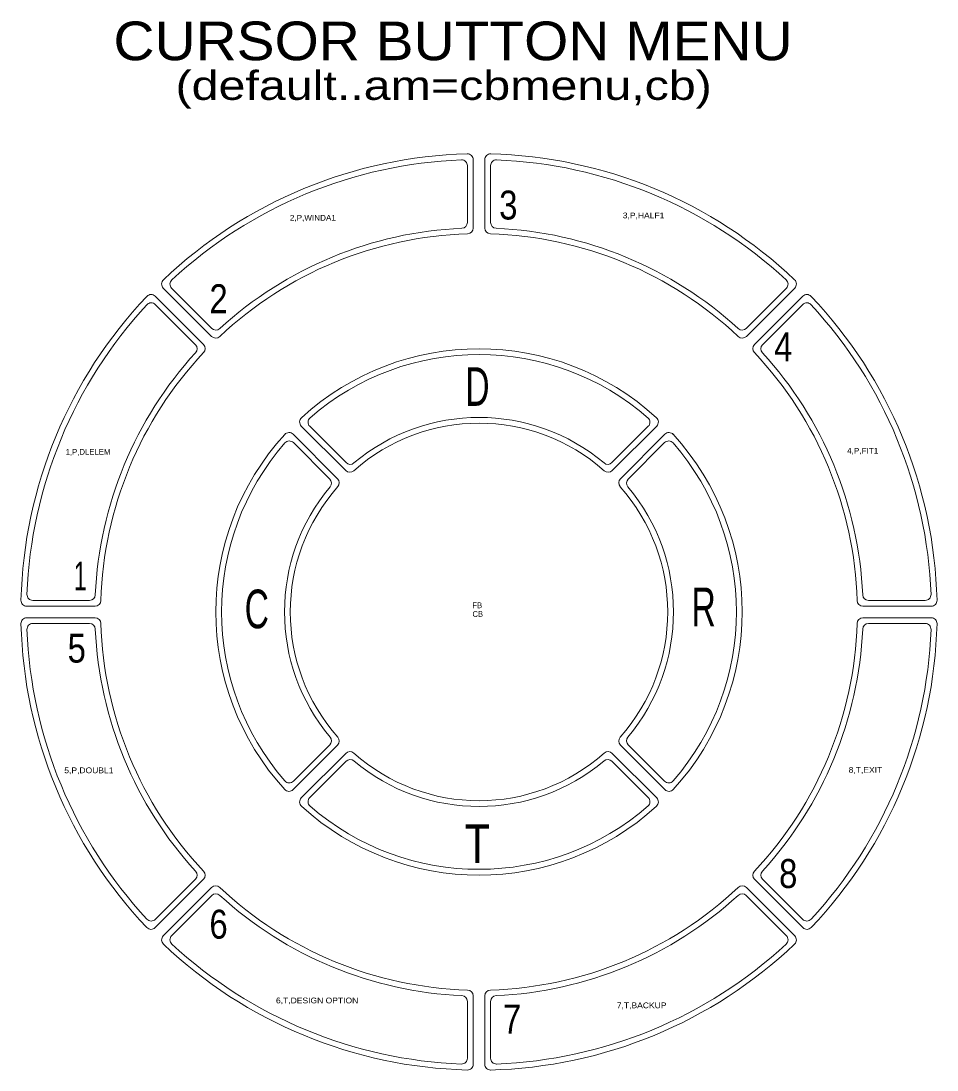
# Model space of a CAD drawing. Extents: x -1.2 to 59.9, y -11 to 7.1.
# Drawn here: x 44.08 to 59.91, y -11.04 to 7.09 of the extents above; entities that cross this region are included whole.
import ezdxf

# ---------------------------------------------------------------- set-up
doc = ezdxf.new("R2010")
doc.units = 0
doc.header["$LTSCALE"] = 0.2
for name, color, linetype, lineweight in [('1', 7, 'Continuous', 13), ('10', 7, 'Continuous', 13), ('4', 7, 'Continuous', 13)]:
    doc.layers.add(name, color=color, linetype=linetype, lineweight=lineweight)
doc.layers.add('63', color=7, linetype='Continuous')

msp = doc.modelspace()

# ---------------------------------------------------------------- linework, layer by layer
at = {"layer": '1'}
for p, q in [((51.7948, 4.5906), (51.7948, 3.609)), ((51.8948, 4.6939), (51.8948, 3.5127)), ((52.0948, 3.5127), (52.0948, 4.6939)), ((52.1948, 3.609), (52.1948, 4.5906)), ((47.3748, 1.6405), (46.5396, 2.4757)), ((47.3775, 1.7794), (46.6834, 2.4735)), ((57.3064, 2.4734), (56.6123, 1.7793)), ((57.4501, 2.4757), (56.6148, 1.6404)), ((47.2333, 1.499), (46.3981, 2.3342)), ((47.0945, 1.4964), (46.4004, 2.1905)), ((57.5916, 2.3342), (56.7563, 1.4989)), ((57.5893, 2.1905), (56.8952, 1.4964)), ((48.9241, 0.0912), (49.6931, -0.6778)), ((49.0697, 0.087), (49.6981, -0.5414)), ((54.92, 0.087), (54.2916, -0.5414)), ((55.0655, 0.0911), (54.2966, -0.6778)), ((49.5516, -0.8193), (48.7826, -0.0503)), ((54.4381, -0.8193), (55.207, -0.0504)), ((49.4152, -0.8243), (48.7868, -0.1959)), ((54.5745, -0.8243), (55.2029, -0.1959)), ((45.361, -3.0211), (44.1798, -3.0211)), ((45.2647, -2.9211), (44.2831, -2.9211)), ((58.6286, -3.0211), (59.8098, -3.0211)), ((58.7249, -2.9211), (59.7065, -2.9211)), ((45.361, -3.2211), (44.1798, -3.2211)), ((58.6286, -3.2211), (59.8098, -3.2211)), ((45.2647, -3.3211), (44.2831, -3.3211)), ((58.7249, -3.3211), (59.7065, -3.3211)), ((49.5515, -5.4229), (48.7826, -6.1918)), ((49.4151, -5.4179), (48.7867, -6.0463)), ((55.2071, -6.1918), (54.4381, -5.4228)), ((55.2029, -6.0462), (54.5745, -5.4178)), ((48.9241, -6.3334), (49.6931, -5.5644)), ((55.0655, -6.3333), (54.2966, -5.5644)), ((49.0697, -6.3292), (49.6981, -5.7008)), ((54.92, -6.3292), (54.2916, -5.7008)), ((47.2333, -7.7411), (46.398, -8.5764)), ((47.0944, -7.7386), (46.4003, -8.4327)), ((56.7564, -7.7411), (57.5916, -8.5763)), ((56.8952, -7.7385), (57.5893, -8.4326)), ((47.3748, -7.8827), (46.5396, -8.7179)), ((57.4501, -8.7179), (56.6148, -7.8826)), ((47.3775, -8.0216), (46.6834, -8.7157)), ((57.3064, -8.7156), (56.6123, -8.0215)), ((51.8948, -10.9361), (51.8948, -9.7549)), ((52.0948, -9.7549), (52.0948, -10.9361)), ((51.7948, -10.8328), (51.7948, -9.8512)), ((52.1948, -9.8512), (52.1948, -10.8328))]:
    msp.add_line(p, q, dxfattribs=at)
for centre, radius, start, end in [((51.9948, -3.1211), 7.9175, 91.46599, 133.53309), ((51.7948, 4.6939), 0.1, 0, 91.46599), ((52.1948, 4.6939), 0.1, 88.53401, 180), ((51.9948, -3.1211), 7.9175, 46.46106, 88.59887), ((51.9948, -3.1211), 7.8175, 92.22779, 132.77033), ((51.6948, 4.5906), 0.1, 0, 92.22779), ((52.2948, 4.5906), 0.1, 87.77221, 180), ((51.9948, -3.1211), 7.8175, 47.22851, 87.82053), ((51.9948, -3.1211), 6.6368, 92.55191, 132.44564), ((51.6948, 3.609), 0.1, 272.55231, 0), ((51.7948, 3.5127), 0.1, 271.72687, 0), ((52.1948, 3.5127), 0.1, 180, 268.27313), ((52.2948, 3.609), 0.1, 180, 267.44769), ((51.9948, -3.1211), 6.6368, 47.55266, 87.44769), ((51.9948, -3.1211), 6.5368, 91.727, 133.27177), ((51.9948, -3.1211), 6.5368, 46.72735, 88.27313), ((46.6103, 2.5464), 0.1, 133.53309, 225), ((46.7541, 2.5442), 0.1, 132.77033, 225), ((57.2356, 2.5441), 0.1, 315, 47.22809), ((57.3794, 2.5464), 0.1, 315, 46.46639), ((46.3274, 2.2635), 0.1, 45, 136.46587), ((57.6623, 2.2635), 0.1, 43.53361, 135), ((46.3297, 2.1198), 0.1, 45, 137.22757), ((57.66, 2.1197), 0.1, 42.77191, 135), ((47.4455, 1.7112), 0.1, 225, 313.27204), ((47.4482, 1.8501), 0.1, 225, 312.44554), ((56.5415, 1.85), 0.1, 227.55266, 315), ((56.5441, 1.7112), 0.1, 226.72735, 315), ((47.0238, 1.4257), 0.1, 317.55206, 45), ((47.1626, 1.4283), 0.1, 316.72674, 45), ((56.8271, 1.4282), 0.1, 135, 223.27265), ((56.9659, 1.4256), 0.1, 135, 222.44734), ((48.9949, 0.1619), 0.1, 132.42079, 225), ((49.1404, 0.1577), 0.1, 131.04141, 225), ((54.8492, 0.1577), 0.1, 315, 48.95766), ((54.9948, 0.1618), 0.1, 315, 47.5783), ((48.7119, -0.121), 0.1, 45, 137.57739), ((48.7161, -0.2666), 0.1, 45, 138.95673), ((55.2736, -0.2667), 0.1, 41.04234, 135), ((55.2777, -0.1211), 0.1, 42.4217, 135), ((49.7688, -0.4707), 0.1, 225, 310.02579), ((54.2209, -0.4707), 0.1, 229.97303, 315), ((49.7638, -0.6071), 0.1, 225, 311.58658), ((54.2259, -0.6071), 0.1, 228.41221, 315), ((49.3445, -0.895), 0.1, 319.97186, 45), ((49.4809, -0.89), 0.1, 318.411, 45), ((54.5088, -0.89), 0.1, 135, 221.58779), ((54.6452, -0.895), 0.1, 135, 220.02697), ((44.2831, -2.8211), 0.1, 177.77221, 270), ((45.2647, -2.8211), 0.1, 270, 357.44769), ((58.7249, -2.8211), 0.1, 182.55231, 270), ((59.7065, -2.8211), 0.1, 270, 2.22779), ((44.1798, -2.9211), 0.1, 178.53401, 270), ((45.361, -2.9211), 0.1, 270, 358.27313), ((58.6286, -2.9211), 0.1, 181.72687, 270), ((59.8098, -2.9211), 0.1, 270, 1.46599), ((44.1798, -3.3211), 0.1, 90, 181.46599), ((45.361, -3.3211), 0.1, 1.72687, 90), ((58.6286, -3.3211), 0.1, 90, 178.27313), ((59.8098, -3.3211), 0.1, 358.53401, 90), ((44.2831, -3.4211), 0.1, 90, 182.22779), ((45.2647, -3.4211), 0.1, 2.55231, 90), ((58.7249, -3.4211), 0.1, 90, 177.44769), ((59.7065, -3.4211), 0.1, 357.77221, 90), ((49.3444, -5.3472), 0.1, 315, 40.02697), ((49.4808, -5.3522), 0.1, 315, 41.58779), ((54.5088, -5.3521), 0.1, 138.41342, 225), ((54.6452, -5.3471), 0.1, 139.97421, 225), ((49.7638, -5.6351), 0.1, 48.41342, 135), ((54.2259, -5.6351), 0.1, 45, 131.58779), ((49.7688, -5.7715), 0.1, 49.97421, 135), ((54.2209, -5.7715), 0.1, 45, 130.02697), ((48.716, -5.9755), 0.1, 221.04234, 315), ((55.2736, -5.9755), 0.1, 225, 318.95859), ((48.7119, -6.1211), 0.1, 222.4217, 315), ((48.9949, -6.4041), 0.1, 135, 227.57921), ((49.1404, -6.3999), 0.1, 135, 228.95859), ((54.8492, -6.3999), 0.1, 311.04234, 45), ((54.9948, -6.404), 0.1, 312.4217, 45), ((55.2778, -6.121), 0.1, 225, 317.57921), ((47.0237, -7.6678), 0.1, 315, 42.44734), ((47.1625, -7.6704), 0.1, 315, 43.27265), ((56.8271, -7.6704), 0.1, 136.72796, 225), ((56.9659, -7.6678), 0.1, 137.55326, 225), ((47.4455, -7.9534), 0.1, 46.72796, 135), ((51.9948, -3.1211), 6.5368, 226.72823, 268.273), ((51.9948, -3.1211), 6.5368, 271.72687, 313.27265), ((56.5441, -7.9534), 0.1, 45, 133.27265), ((47.4482, -8.0923), 0.1, 47.55446, 135), ((51.9948, -3.1211), 6.6368, 227.55436, 267.44809), ((51.9948, -3.1211), 6.6368, 272.55231, 312.44734), ((56.5415, -8.0922), 0.1, 45, 132.44734), ((46.3296, -8.3619), 0.1, 222.77191, 315), ((57.66, -8.3619), 0.1, 225, 317.22862), ((46.3273, -8.5057), 0.1, 223.53361, 315), ((57.6623, -8.5056), 0.1, 225, 316.46691), ((46.6103, -8.7886), 0.1, 135, 226.46691), ((51.9948, -3.1211), 7.9175, 226.46691, 268.53401), ((46.7541, -8.7864), 0.1, 135, 227.22967), ((51.9948, -3.1211), 7.8175, 227.22967, 267.77221), ((51.9948, -3.1211), 7.9175, 271.40113, 313.53894), ((51.9948, -3.1211), 7.8175, 272.17947, 312.77149), ((57.2356, -8.7863), 0.1, 312.77191, 45), ((57.3794, -8.7886), 0.1, 313.53361, 45), ((51.6948, -9.8512), 0.1, 0, 87.44769), ((51.7948, -9.7549), 0.1, 0, 88.27313), ((52.1948, -9.7549), 0.1, 91.72687, 180), ((52.2948, -9.8512), 0.1, 92.55231, 180), ((51.6948, -10.8328), 0.1, 267.77221, 0), ((52.2948, -10.8328), 0.1, 180, 272.22779), ((51.7948, -10.9361), 0.1, 268.53401, 0), ((52.1948, -10.9361), 0.1, 180, 271.46599)]:
    msp.add_arc(centre, radius, start, end, dxfattribs=at)
at = {"layer": '10'}
for radius, start, end in [(7.9175, 136.46588, 178.53401), (7.8175, 137.22757, 177.77221), (7.8175, 2.19928, 42.80053), (7.9175, 1.46599, 43.5333), (6.6368, 137.55192, 177.44809), (6.5368, 136.72699, 178.273), (4.5472, 47.57756, 132.42066), (4.4472, 48.86849, 131.04218), (6.5368, 1.72687, 43.27265), (6.6368, 2.55231, 42.44734), (3.3612, 49.97303, 130.02535), (3.2612, 48.41221, 131.58656), (4.5472, 137.57739, 222.42244), (4.5472, 317.57921, 42.47856), (4.4472, 138.95673, 221.04219), (4.4472, 318.95859, 41.04218), (3.3612, 139.97225, 220.02697), (3.2612, 138.41096, 221.58779), (3.2612, 318.41344, 41.58779), (3.3612, 319.97465, 40.02697), (7.8175, 2.19901, 2.22779), (7.9175, 181.46628, 223.5333), (7.8175, 182.19928, 222.77149), (6.6368, 182.55231, 222.44734), (6.5368, 181.72687, 223.27265), (6.5368, 316.72823, 358.273), (6.6368, 317.55314, 357.44809), (7.8175, 317.22862, 357.77221), (7.9175, 316.46691, 358.53401), (3.2612, 228.41344, 311.58779), (3.3612, 229.97465, 310.02697), (4.5472, 227.57934, 312.42244), (4.4472, 228.95782, 311.13151)]:
    msp.add_arc((51.9948, -3.1211), radius, start, end, dxfattribs=at)

# ---------------------------------------------------------------- texts
at = {"layer": '1'}
for s, width, p in [('(default..am=cbmenu,cb)', 1.25, (46.7503, 5.7269)), ('3', 0.85, (52.3433, 3.6598)), ('2', 0.85, (47.3358, 2.0409)), ('4', 0.85, (57.0951, 1.2096)), ('1', 0.6, (44.9918, -2.7501)), ('5', 0.85, (44.8853, -3.9971)), ('8', 0.85, (57.1803, -7.8912)), ('6', 0.85, (47.3358, -8.7663)), ('7', 0.85, (52.4072, -10.407))]:
    msp.add_text(s, height=0.5, dxfattribs=dict(at, width=width)).set_placement(p)
at = {"layer": '4'}
for s, width, p in [('CURSOR BUTTON MENU', 1.1, (45.6776, 6.4123)), ('D', 0.65, (51.7577, 0.4401)), ('R', 0.65, (55.6673, -3.3679)), ('C', 0.65, (47.9452, -3.4032)), ('T', 0.8, (51.7472, -7.4581))]:
    msp.add_text(s, height=0.668, dxfattribs=dict(at, width=width)).set_placement(p)
at = {"layer": '63'}
for s, width, p in [('2,P,WINDA1', 1.05, (48.7262, 3.6391)), ('3,P,HALF1', 1.1, (54.4787, 3.6798)), ('4,P,FIT1', 1.05, (58.3562, -0.3865)), ('FB', 0.95, (51.8823, -3.0564)), ('CB', 0.9, (51.8823, -3.2064)), ('8,T,EXIT', 1.1, (58.383, -5.9009)), ('5,P,DOUBL1', 1.1, (44.8279, -5.9078)), ('6,T,DESIGN OPTION', 1.1, (48.4862, -9.8846)), ('7,T,BACKUP', 1.1, (54.3765, -9.9687))]:
    msp.add_text(s, height=0.1, dxfattribs=dict(at, width=width)).set_placement(p)
msp.add_text('1,P,DLELEM', height=0.1, dxfattribs=at).set_placement((44.8518, -0.4056))

doc.saveas('drawing.dxf')
